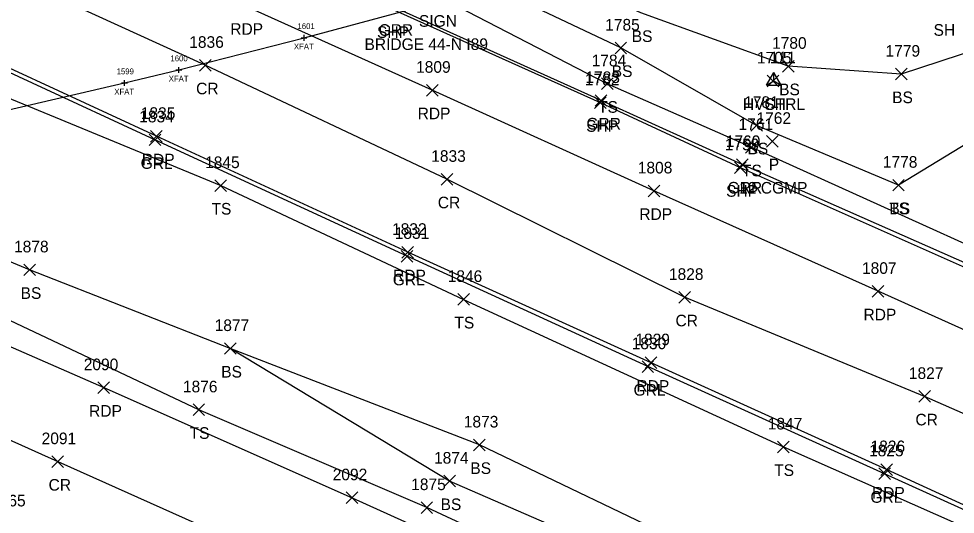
# Model space of a CAD drawing. Extents: x 1599569 to 1610055, y 642560 to 647860.
# Drawn here: x 1601651.7 to 1601812.9, y 647204.6 to 647289.9 of the extents above; entities that cross this region are included whole.
import ezdxf

# ---------------------------------------------------------------- set-up
doc = ezdxf.new("R2010")
doc.units = 0
for name, color, linetype in [('B_A', 7, 'Continuous'), ('B_I', 7, 'Continuous'), ('B_TIC', 7, 'Continuous'), ('BF', 7, 'Continuous'), ('C_A', 7, 'Continuous'), ('C_I', 7, 'Continuous'), ('CPSM', 7, 'Continuous'), ('D_A', 7, 'Continuous'), ('D_C', 7, 'Continuous'), ('D_I', 7, 'Continuous'), ('D_TIC', 7, 'Continuous'), ('L_A', 7, 'Continuous'), ('L_I', 7, 'Continuous'), ('L_TIC', 7, 'Continuous'), ('LELB', 7, 'Continuous'), ('P_A', 7, 'Continuous'), ('P_I', 7, 'Continuous'), ('P_TIC', 7, 'Continuous'), ('PET', 7, 'Continuous'), ('PRC', 7, 'Continuous'), ('PSP', 7, 'Continuous'), ('R_A', 7, 'Continuous'), ('R_I', 7, 'Continuous'), ('R_TIC', 7, 'Continuous'), ('RGR', 7, 'Continuous'), ('S_A', 7, 'Continuous'), ('S_C', 7, 'Continuous')]:
    doc.layers.add(name, color=color, linetype=linetype)

msp = doc.modelspace()

# ---------------------------------------------------------------- linework, layer by layer
at = {"layer": 'B_TIC'}
for p, q in [((1601700.8, 647286.58), (1601700.87, 647286.58)), ((1601679.25, 647281.04), (1601679.33, 647281.04)), ((1601669.89, 647278.8), (1601669.97, 647278.8))]:
    msp.add_line(p, q, dxfattribs=at)
for points in [[(1601700.3, 647286.58), (1601701.3, 647286.58)], [(1601700.8, 647286.08), (1601700.8, 647287.08)], [(1601679.25, 647280.54), (1601679.25, 647281.54)], [(1601678.75, 647281.04), (1601679.75, 647281.04)], [(1601669.39, 647278.8), (1601670.39, 647278.8)], [(1601669.89, 647278.3), (1601669.89, 647279.3)]]:
    msp.add_lwpolyline(points, dxfattribs=at)
at = {"layer": 'BF'}
msp.add_lwpolyline([(1601649.72, 647274.11), (1601669.89, 647278.8), (1601679.25, 647281.04), (1601700.8, 647286.58), (1601721.51, 647292.14), (1601745.83, 647299.07), (1601773.93, 647307.75), (1601791.77, 647313.46), (1601791.43, 647314.29)], dxfattribs=at)
at = {"layer": 'CPSM'}
for p, q in [((1601780.39, 647278.45), (1601781.64, 647280.62)), ((1601782.89, 647278.45), (1601781.64, 647280.62)), ((1601781.64, 647279.17), (1601781.64, 647280.62)), ((1601780.39, 647278.45), (1601781.64, 647279.17)), ((1601780.39, 647278.45), (1601782.89, 647278.45)), ((1601781.64, 647279.17), (1601781.64, 647279.17)), ((1601781.64, 647279.17), (1601782.89, 647278.45))]:
    msp.add_line(p, q, dxfattribs=at)
at = {"layer": 'D_TIC'}
for points in [[(1601780.41, 647267.76), (1601782.41, 647269.76)], [(1601782.41, 647267.76), (1601780.41, 647269.76)]]:
    msp.add_lwpolyline(points, dxfattribs=at)
at = {"layer": 'L_TIC'}
for points in [[(1601754.32, 647283.83), (1601756.32, 647285.83)], [(1601756.32, 647283.83), (1601754.32, 647285.83)], [(1601783.13, 647280.69), (1601785.13, 647282.69)], [(1601785.13, 647280.69), (1601783.13, 647282.69)], [(1601802.58, 647279.33), (1601804.58, 647281.33)], [(1601804.58, 647279.33), (1601802.58, 647281.33)], [(1601751.99, 647277.68), (1601753.99, 647279.68)], [(1601753.99, 647277.68), (1601751.99, 647279.68)], [(1601780.53, 647278.16), (1601782.53, 647280.16)], [(1601782.53, 647278.16), (1601780.53, 647280.16)], [(1601777.68, 647270.51), (1601779.68, 647272.51)], [(1601779.68, 647270.51), (1601777.68, 647272.51)], [(1601776.77, 647266.73), (1601778.77, 647268.73)], [(1601778.77, 647266.73), (1601776.77, 647268.73)], [(1601685.47, 647260.15), (1601687.47, 647262.15)], [(1601687.47, 647260.15), (1601685.47, 647262.15)], [(1601802.11, 647260.21), (1601804.11, 647262.21)], [(1601804.11, 647260.21), (1601802.11, 647262.21)], [(1601802.11, 647260.21), (1601804.11, 647262.21)], [(1601804.11, 647260.21), (1601802.11, 647262.21)], [(1601652.57, 647245.64), (1601654.57, 647247.64)], [(1601654.57, 647245.64), (1601652.57, 647247.64)], [(1601727.27, 647240.55), (1601729.27, 647242.55)], [(1601729.27, 647240.55), (1601727.27, 647242.55)], [(1601687.1, 647232.1), (1601689.1, 647234.1)], [(1601689.1, 647232.1), (1601687.1, 647234.1)], [(1601687.1, 647232.1), (1601689.1, 647234.1)], [(1601689.1, 647232.1), (1601687.1, 647234.1)], [(1601681.69, 647221.55), (1601683.69, 647223.55)], [(1601683.69, 647221.55), (1601681.69, 647223.55)], [(1601729.98, 647215.5), (1601731.98, 647217.5)], [(1601731.98, 647215.5), (1601729.98, 647217.5)], [(1601782.31, 647215.16), (1601784.31, 647217.16)], [(1601784.31, 647215.16), (1601782.31, 647217.16)], [(1601724.86, 647209.28), (1601726.86, 647211.28)], [(1601726.86, 647209.28), (1601724.86, 647211.28)], [(1601720.93, 647204.72), (1601722.93, 647206.72)], [(1601722.93, 647204.72), (1601720.93, 647206.72)]]:
    msp.add_lwpolyline(points, dxfattribs=at)
at = {"layer": 'LELB'}
for points in [[(1601850.43, 647302.21), (1601817.07, 647284.74), (1601803.58, 647280.33), (1601784.13, 647281.69), (1601758.75, 647290.86), (1601723.07, 647307), (1601685.47, 647323.96), (1601675.62, 647324.78), (1601658.01, 647334.35), (1601634.9, 647343.88), (1601612.64, 647349.36), (1601572.76, 647365.6), (1601544.62, 647379.24), (1601520.15, 647401.41)], [(1601803.11, 647261.21), (1601778.68, 647271.51), (1601755.32, 647284.83), (1601720.1, 647301.53), (1601682.66, 647319.41), (1601674.11, 647321.15), (1601654.95, 647329.02), (1601631.94, 647340.27), (1601610.73, 647346.29), (1601571.98, 647363.61), (1601543.15, 647377.5), (1601514.76, 647392.23)], [(1602123.64, 647113.01), (1602089.26, 647126.92), (1602047.74, 647146.19), (1602004.2, 647166.45), (1601956.69, 647187.25), (1601908.21, 647210.05), (1601851.73, 647234.01), (1601822.38, 647247.53), (1601777.77, 647267.73), (1601752.99, 647278.68), (1601718.68, 647296.47)], [(1601871.56, 647297.15), (1601825.85, 647275.03), (1601803.11, 647261.21)], [(1601962.97, 647113.31), (1601923.69, 647130.08), (1601895.55, 647143.8), (1601852.73, 647162.89), (1601817.77, 647178.58), (1601769.5, 647198.02), (1601730.98, 647216.5), (1601688.1, 647233.1), (1601653.57, 647246.64), (1601608.27, 647265.53), (1601581.18, 647285.19)], [(1601646.77, 647277.53), (1601686.47, 647261.15), (1601728.27, 647241.55), (1601783.31, 647216.16), (1601831.6, 647194.79), (1601880.63, 647172.23), (1601925.63, 647152.36), (1601972.37, 647131.79)], [(1601955.14, 647100.52), (1601918.75, 647116.38), (1601885.72, 647130.9), (1601846.21, 647148.37), (1601809.11, 647165.35), (1601762.69, 647186.72), (1601721.93, 647205.72), (1601682.69, 647222.55), (1601645.99, 647239.88), (1601604.12, 647258.19), (1601590.91, 647265.16)], [(1601961.31, 647109.79), (1601923.17, 647125.81), (1601892.78, 647139.96), (1601850.81, 647159.82), (1601815.66, 647174.43), (1601765.95, 647192.8), (1601725.86, 647210.28), (1601688.1, 647233.1)]]:
    msp.add_lwpolyline(points, dxfattribs=at)
at = {"layer": 'P_TIC'}
for points in [[(1601682.79, 647280.85), (1601684.79, 647282.85)], [(1601684.79, 647280.85), (1601682.79, 647282.85)], [(1601721.86, 647276.56), (1601723.86, 647278.56)], [(1601723.86, 647276.56), (1601721.86, 647278.56)], [(1601750.81, 647274.4), (1601752.81, 647276.4)], [(1601752.81, 647274.4), (1601750.81, 647276.4)], [(1601674.39, 647268.62), (1601676.39, 647270.62)], [(1601676.39, 647268.62), (1601674.39, 647270.62)], [(1601774.91, 647263.22), (1601776.91, 647265.22)], [(1601776.91, 647263.22), (1601774.91, 647265.22)], [(1601724.38, 647261.23), (1601726.38, 647263.23)], [(1601726.38, 647261.23), (1601724.38, 647263.23)], [(1601760.01, 647259.23), (1601762.01, 647261.23)], [(1601762.01, 647259.23), (1601760.01, 647261.23)], [(1601717.64, 647248.66), (1601719.64, 647250.66)], [(1601719.64, 647248.66), (1601717.64, 647250.66)], [(1601765.29, 647240.91), (1601767.29, 647242.91)], [(1601767.29, 647240.91), (1601765.29, 647242.91)], [(1601798.6, 647241.94), (1601800.6, 647243.94)], [(1601800.6, 647241.94), (1601798.6, 647243.94)], [(1601759.52, 647229.65), (1601761.52, 647231.65)], [(1601761.52, 647229.65), (1601759.52, 647231.65)], [(1601665.31, 647225.36), (1601667.31, 647227.36)], [(1601667.31, 647225.36), (1601665.31, 647227.36)], [(1601806.6, 647223.86), (1601808.6, 647225.86)], [(1601808.6, 647223.86), (1601806.6, 647225.86)], [(1601657.4, 647212.63), (1601659.4, 647214.63)], [(1601659.4, 647212.63), (1601657.4, 647214.63)], [(1601800.06, 647211.25), (1601802.06, 647213.25)], [(1601802.06, 647211.25), (1601800.06, 647213.25)], [(1601708.07, 647206.41), (1601710.07, 647208.41)], [(1601710.07, 647206.41), (1601708.07, 647208.41)]]:
    msp.add_lwpolyline(points, dxfattribs=at)
at = {"layer": 'PET'}
for points in [[(1602047.79, 647130.94), (1602008.9, 647148.2), (1601944.5, 647177.36), (1601896.5, 647199.08), (1601839.98, 647224.8), (1601799.6, 647242.94), (1601761.01, 647260.23), (1601722.86, 647277.56), (1601690.61, 647292.09), (1601662.07, 647305.04), (1601633.77, 647318.29), (1601601.82, 647332.75), (1601566.11, 647348.71), (1601533.57, 647363.83), (1601469.6, 647392.2)], [(1601973.38, 647134.15), (1601930.79, 647153.54), (1601888.64, 647172.44), (1601843.17, 647192.94), (1601801.06, 647212.25), (1601760.52, 647230.65), (1601718.64, 647249.66), (1601675.39, 647269.62), (1601633.17, 647289.14), (1601607.86, 647300.47), (1601588.56, 647309.14), (1601555.09, 647324.12), (1601512, 647343.16), (1601472.14, 647361.1), (1601457.8, 647367.35)], [(1601401.84, 647345.99), (1601436.76, 647329.85), (1601477.89, 647310.69), (1601511.69, 647295.64), (1601529.2, 647287.58), (1601568.21, 647270.13), (1601613.57, 647249.46), (1601666.31, 647226.36), (1601709.07, 647207.41), (1601751.08, 647188.42), (1601796.47, 647168.32), (1601839.63, 647148.76), (1601881.89, 647129.58), (1601912.89, 647115.63)]]:
    msp.add_lwpolyline(points, dxfattribs=at)
at = {"layer": 'PRC'}
for points in [[(1602004.91, 647136.4), (1601979.09, 647147.72), (1601938.18, 647166.06), (1601894.66, 647185.48), (1601851.67, 647205.52), (1601807.6, 647224.86), (1601766.29, 647241.91), (1601725.38, 647262.23), (1601683.79, 647281.85), (1601638.16, 647302.69), (1601616.13, 647312.82), (1601597.54, 647321.11), (1601562.74, 647336.75), (1601520.64, 647355.15), (1601479.31, 647373.89)], [(1601345.39, 647355.71), (1601383.98, 647338.31), (1601428.29, 647317.74), (1601472.83, 647297.09), (1601504.71, 647281.99), (1601534.71, 647269.01), (1601561.28, 647257.19), (1601605.65, 647237.34), (1601658.4, 647213.63), (1601702.28, 647194), (1601743.84, 647175.46), (1601792.12, 647154.22), (1601833.09, 647135.23), (1601874.76, 647116.71)]]:
    msp.add_lwpolyline(points, dxfattribs=at)
at = {"layer": 'PSP'}
msp.add_lwpolyline([(1602119.04, 647109.91), (1602086.42, 647124.41), (1602045.38, 647142.93), (1602000.82, 647163.15), (1601951.88, 647184.91), (1601900.46, 647208.01), (1601848.64, 647231.74), (1601816.21, 647246.31), (1601775.91, 647264.22), (1601751.81, 647275.4), (1601715.81, 647291.56), (1601673.9, 647310.83), (1601638.2, 647326.96), (1601607.44, 647341.11), (1601569.57, 647358.04), (1601539.77, 647371.54), (1601489.48, 647394.4)], dxfattribs=at)
at = {"layer": 'R_TIC'}
for points in [[(1601750.92, 647274.79), (1601752.92, 647276.79)], [(1601752.92, 647274.79), (1601750.92, 647276.79)], [(1601674.12, 647268.02), (1601676.12, 647270.02)], [(1601676.12, 647268.02), (1601674.12, 647270.02)], [(1601775.21, 647263.77), (1601777.21, 647265.77)], [(1601777.21, 647263.77), (1601775.21, 647265.77)], [(1601717.53, 647247.97), (1601719.53, 647249.97)], [(1601719.53, 647247.97), (1601717.53, 647249.97)], [(1601758.97, 647228.98), (1601760.97, 647230.98)], [(1601760.97, 647228.98), (1601758.97, 647230.98)], [(1601799.73, 647210.54), (1601801.73, 647212.54)], [(1601801.73, 647210.54), (1601799.73, 647212.54)]]:
    msp.add_lwpolyline(points, dxfattribs=at)
at = {"layer": 'RGR'}
for points in [[(1601973.06, 647133.72), (1601930.49, 647152.82), (1601887.99, 647171.84), (1601842.93, 647192.4), (1601800.73, 647211.54), (1601759.97, 647229.98), (1601718.53, 647248.97), (1601675.12, 647269.02), (1601632.93, 647288.53), (1601607.5, 647300), (1601588.34, 647308.52), (1601554.72, 647323.41), (1601511.66, 647342.62), (1601471.88, 647360.48), (1601457.01, 647367.11)], [(1602119.22, 647110.24), (1602086.6, 647124.69), (1602045.91, 647143.17), (1602000.94, 647163.41), (1601952.66, 647185.37), (1601901.1, 647208.39), (1601848.7, 647232.28), (1601817.54, 647246.54), (1601776.21, 647264.77), (1601751.92, 647275.79), (1601716.14, 647291.92), (1601674.23, 647311.09), (1601638.71, 647327.76)]]:
    msp.add_lwpolyline(points, dxfattribs=at)

# ---------------------------------------------------------------- texts
at = {"layer": 'B_A'}
for p in [(1601699.05, 647284.58), (1601677.5, 647279.04), (1601668.14, 647276.8)]:
    msp.add_text('XFAT', height=1, dxfattribs=at).set_placement(p)
at = {"layer": 'B_I'}
for s, p in [('1601', (1601699.67, 647288.08)), ('1600', (1601677.8, 647282.54)), ('1599', (1601668.54, 647280.3))]:
    msp.add_text(s, height=1, dxfattribs=at).set_placement(p)
at = {"layer": 'C_A'}
msp.add_text('HVCTRL', height=2, dxfattribs=at).set_placement((1601776.33, 647274.17))
at = {"layer": 'C_I'}
msp.add_text('111', height=2, dxfattribs=at).set_placement((1601780.97, 647282.17))
at = {"layer": 'D_A'}
msp.add_text('P', height=2, dxfattribs=at).set_placement((1601780.79, 647263.76))
at = {"layer": 'D_C'}
msp.add_text('12 CGMP', height=2, dxfattribs=at).set_placement((1601775.7, 647259.76))
at = {"layer": 'D_I'}
msp.add_text('1762', height=2, dxfattribs=at).set_placement((1601778.67, 647271.76))
at = {"layer": 'L_A'}
for s, p in [('BS', (1601757.2, 647285.86)), ('SH', (1601809.15, 647286.93)), ('BS', (1601753.76, 647279.83)), ('BS', (1601782.57, 647276.69)), ('BS', (1601802.02, 647275.33)), ('TS', (1601751.4, 647273.68)), ('SH', (1601780.01, 647274.16)), ('BS', (1601777.12, 647266.51)), ('TS', (1601776.18, 647262.73)), ('TS', (1601684.87, 647256.15)), ('TS', (1601801.52, 647256.21)), ('BS', (1601801.55, 647256.21)), ('BS', (1601652.01, 647241.64)), ('TS', (1601726.68, 647236.55)), ('BS', (1601686.54, 647228.1)), ('BS', (1601686.54, 647228.1)), ('TS', (1601681.1, 647217.55)), ('BS', (1601729.42, 647211.5)), ('TS', (1601781.72, 647211.16)), ('BS', (1601724.3, 647205.28))]:
    msp.add_text(s, height=2, dxfattribs=at).set_placement(p)
at = {"layer": 'L_I'}
for s, p in [('1785', (1601752.63, 647287.83)), ('1780', (1601781.35, 647284.69)), ('1779', (1601800.88, 647283.33)), ('1784', (1601750.3, 647281.68)), ('1705', (1601778.75, 647282.16)), ('1781', (1601776.55, 647274.51)), ('1761', (1601775.59, 647270.73)), ('1845', (1601683.77, 647264.15)), ('1778', (1601800.42, 647264.21)), ('1778', (1601800.42, 647264.21)), ('1878', (1601650.88, 647249.64)), ('1846', (1601725.52, 647244.55)), ('1877', (1601685.41, 647236.1)), ('1877', (1601685.41, 647236.1)), ('1876', (1601679.95, 647225.55)), ('1873', (1601728.29, 647219.5)), ('1847', (1601780.61, 647219.16)), ('1874', (1601723.17, 647213.28)), ('1875', (1601719.24, 647208.72))]:
    msp.add_text(s, height=2, dxfattribs=at).set_placement(p)
at = {"layer": 'P_A'}
for s, p in [('RDP', (1601688.1, 647287.09)), ('SHP', (1601713.35, 647286.56)), ('CR', (1601682.22, 647276.85)), ('RDP', (1601720.35, 647272.56)), ('SHP', (1601749.35, 647270.4)), ('RDP', (1601672.88, 647264.62)), ('SHP', (1601773.44, 647259.22)), ('CR', (1601723.82, 647257.23)), ('RDP', (1601758.5, 647255.23)), ('RDP', (1601716.12, 647244.66)), ('RDP', (1601797.09, 647237.94)), ('CR', (1601764.73, 647236.91)), ('RDP', (1601758.01, 647225.65)), ('RDP', (1601663.8, 647221.36)), ('CR', (1601806.03, 647219.86)), ('CR', (1601656.83, 647208.63)), ('RDP', (1601798.55, 647207.25))]:
    msp.add_text(s, height=2, dxfattribs=at).set_placement(p)
at = {"layer": 'P_I'}
for s, p in [('1836', (1601681.04, 647284.85)), ('1809', (1601720.08, 647280.56)), ('1782', (1601749.12, 647278.4)), ('1835', (1601672.7, 647272.62)), ('1759', (1601773.21, 647267.22)), ('1833', (1601722.69, 647265.23)), ('1808', (1601758.24, 647263.23)), ('1832', (1601715.94, 647252.66)), ('1807', (1601796.83, 647245.94)), ('1828', (1601763.6, 647244.91)), ('1829', (1601757.82, 647233.65)), ('2090', (1601662.88, 647229.36)), ('1827', (1601804.9, 647227.86)), ('2091', (1601655.63, 647216.63)), ('1826', (1601798.31, 647215.25)), ('2092', (1601705.73, 647210.41)), ('2065', (1601646.93, 647205.92))]:
    msp.add_text(s, height=2, dxfattribs=at).set_placement(p)
at = {"layer": 'R_A'}
for s, p in [('GRR', (1601713.63, 647286.92)), ('GRR', (1601749.4, 647270.79)), ('GRL', (1601672.67, 647264.02)), ('GRR', (1601773.7, 647259.77)), ('GRL', (1601716.07, 647243.97)), ('GRL', (1601757.51, 647224.98)), ('GRL', (1601798.28, 647206.54))]:
    msp.add_text(s, height=2, dxfattribs=at).set_placement(p)
at = {"layer": 'R_I'}
for s, p in [('1783', (1601749.22, 647278.79)), ('1834', (1601672.43, 647272.02)), ('1760', (1601773.38, 647267.77)), ('1831', (1601716.4, 647251.97)), ('1830', (1601757.19, 647232.98)), ('1825', (1601798.04, 647214.54))]:
    msp.add_text(s, height=2, dxfattribs=at).set_placement(p)
at = {"layer": 'S_A'}
msp.add_text('SIGN', height=2, dxfattribs=at).set_placement((1601720.57, 647288.48))
at = {"layer": 'S_C'}
msp.add_text('BRIDGE 44-N I89', height=2, dxfattribs=at).set_placement((1601711.2, 647284.48))

doc.saveas('drawing.dxf')
